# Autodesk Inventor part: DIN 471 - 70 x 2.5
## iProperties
Created: 2008-08
Part Number: DIN 471 - 70 x 2.5
Material: BgAAAEgAAABOAEEATQBFAFMACgBNAGEAdABlAHIAaQBhAGwAcwAKADEAOgBTAHQAZQBlAGwALAAgAE0AaQBsAGQACgAKAEUATgBEAAoAAAA=
Description: Sicherungsring
Vendor: Autodesk Inc.
Document SubType Name: Modeling
Standard: DIN 471
Designer: U.Rapp
Standards Organization: DIN
Language: de-DE
Size Designation: 70 x 2.5
Categories: <MemberInstance Version="R10.0.0"><Categories><Category DisplayName="Wellenteile" InternalName="7f7aeb1f-a693-4053-b835-cee3144e0d98" Mnemonic="SHFT"><Category
Author: U.Rapp
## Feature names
1. Körper [Extrusion]
